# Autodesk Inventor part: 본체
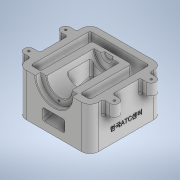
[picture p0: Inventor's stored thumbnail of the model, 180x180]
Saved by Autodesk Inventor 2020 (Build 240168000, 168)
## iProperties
Created: 2022-03
Part Number: 본체
Material: 일반
Document SubType Name: Modeling
Designer: Administrator
Density: 1 g/cm^3
Appearance: 기본값
Author: Administrator
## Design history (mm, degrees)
sketch "스케치1"
  geometry: L1 (-55, -55)-(55, -55); L2 (55, -55)-(55, 55); L3 (55, 55)-(-55, 55); L4 (-55, 55)-(-55, -55); L5 (-55, -55)-(55, 55); L6 (55, -55)-(-55, 55); 1 further point
  constraints: 12 end point, 2 midpoint, 2 parallel, 1 horizontal, 1 perpendicular
  dimensions: "d0" = 110 distance of L2.end L3.end; "d1" = 110 distance of L3.end L1.start
extrude "돌출1" new body sketch "스케치1" distance "d2" = 65; taper "d3" = 0 deg
sketch "스케치3"
  geometry: L1 (-45, 45)-(45, 45); L2 (-45, 45)-(-45, -45); L3 (-45, -45)-(-30, -45); L4 (-30, -45)-(-30, 33); L5 (-30, 33)-(30, 33); L6 (30, 33)-(30, -45); L7 (45, 45)-(45, -45); L8 (45, -45)-(30, -45); L9 (-55, 55)-(-55, -55) reference; L10 (55, -55)-(55, 55) reference; L11 (55, 55)-(-55, 55) reference; L12 (-55, -55)-(55, -55) reference; 1 further point
  constraints: 16 end point, 5 perpendicular, 2 vertical, 1 horizontal, 1 point on line
  dimensions: "d5" = 25 distance between parallel lines of L4 L9; "d7" = 25 distance between parallel lines of L6 L10; "d8" = 10 distance between parallel lines of L1 L11; "d9" = 12 distance between parallel lines of L1 L5; "d10" = 15 distance between parallel lines of L4 L2; "d11" = 15 distance between parallel lines of L6 L7; "d12" = 10 distance between parallel lines of L12 L3
extrude "돌출2" cut sketch "스케치3" extent not by distance; stored distance "d13" = 0; taper "d14" = 0 deg
sketch "스케치5"
  geometry: L1 (55, 65)-(-55, 65) reference; L2 (-55, 65)-(55, 65); L3 (-55, 0)-(-55, 65) reference; L4 (-55, 65)-(-55, 37); L5 (-55, 37)-(-47, 37); L6 (-45, 65)-(-45, 0) reference; L7 (-47, 37)-(-47, 46); L8 (-47, 46)-(25, 46); L9 (25, 46)-(25, 65); 2 further points
  constraints: 12 end point, 3 perpendicular, 2 point on line, 1 horizontal, 1 parallel
  dimensions: "d16" = 8 distance of L4.end L5.end; "d17" = 56 diameter of L5 L1; "d18" = 38 diameter of L8 L1; "d19" = 72 distance between parallel lines of L9 L7
revolve "회전1" sketch "스케치5" stored, may be unused: angle "d20" = 90 deg
node "작업 평면1"
sketch "스케치6"
  geometry: L1 (19, 0)-(-19, 0) reference; C1 r 6.5 at (0, 0); 3 further points
  constraints: 1 centre point, 1 midpoint
  dimensions: "d22" = 13 diameter of C1
extrude "돌출4" cut sketch "스케치6" stored distance "d25" = 10; taper "d26" = 30 deg
fillet "모깎기1" dims "d27" = 13
sketch "스케치7"
  geometry: L1 (-65, 35)-(-47.997, 35); L2 (-47.997, 35)-(-47.997, 21); L3 (-47.997, 21)-(-65, 21); L4 (-45, -45)-(-45, 45) reference; L5 (-55, 42)-(-55, -42) reference; L6 (42, 55)-(-42, 55) reference; A1 r 7 centre (-65, 28) between (-65, 35) and (-65, 21); 3 further points
  constraints: 6 end point, 2 point on circle, 1 centre point, 1 horizontal, 1 perpendicular, 1 tangent, 1 vertical alignment
  dimensions: "d29" = 10 distance from line of A1.centre L5; "d30" = 14 distance between parallel lines of L3 L1; "d31" = 27 distance from line of A1.centre L6
extrude "돌출5" join sketch "스케치7" distance "d32" = 20; taper "d33" = 0 deg
chamfer "모따기1" distance "d34" = 1; stored, may be unused: second distance "d35" = 2, angle "d36" = 45 deg
sketch "스케치8"
  geometry: A1 r 7 centre (-65, 28) between (-65, 35) and (-65, 21) reference; A2 r 7 centre (-65, -28) between (-65, -21) and (-65, -35) reference; A3 r 7 centre (65, -28) between (65, -35) and (65, -21) reference; A4 r 7 centre (65, 28) between (65, 21) and (65, 35) reference; 5 further points
  constraints: 4 coincident
hole "구멍1" sketch "스케치8" at (-65, 28), (-65, -28), (65, -28), (65, 28) diameter "d37" = 3.242; stored, may be unused: countersink angle "d41" = 90 deg, drill point angle "d43" = 118 deg; dims "d38" = 9, "d39" = 4, "d40" = 2, "d42" = 11
fillet "모깎기2" dims "d44" = 3
fillet "모깎기3" dims "d45" = 3
chamfer "모따기2" distance "d46" = 1; stored, may be unused: second distance "d47" = 2, angle "d48" = 45 deg
sketch "스케치10"
  geometry: L1 (-55, 0)-(-55, 65) reference; L2 (-55, 29.197)-(-19, 38.843); L3 (-55, 11.597)-(19, 31.425); L4 (33, 65)-(33, 0) reference; L5 (33, 30)-(-36.449, 11.391); L6 (-36.449, 11.391)-(-36.449, 0); L7 (-45, 0)-(33, 0) reference; L8 (-19, 57.482)-(19, 57.482); L9 (-19, 57.482)-(-19, 38.843); L10 (-18, 65)-(-18, 48) reference; L11 (19, 57.482)-(19, 31.425); L12 (18, 48)-(18, 65) reference; L13 (-55, 29.197)-(-55, 11.597); 1 further point
  constraints: 16 end point, 5 parallel, 4 point on line, 1 horizontal, 1 vertical
  dimensions: "d50" = 17 distance between parallel lines of L3 L2; "d51" = 30 distance from line of L5.start L7; "d52" = 75 deg angle of L4 L5; "d53" = 5 distance between parallel lines of L3 L5; "d54" = 36 distance from line of L8.start L1; "d55" = 38 distance of L8.end L8.start
extrude "돌출6" cut sketch "스케치10" stored distance "d56" = 34; taper "d57" = 0 deg
fillet "모깎기4" dims "d58" = 3
fillet "모깎기5" dims "d59" = 3
sketch "스케치11"
  geometry: L1 (0, 0)-(0, 84) reference; 3 further points
  constraints: 1 horizontal alignment, 1 midpoint, 1 other
  dimensions: "d60" = 20 distance of point (-20, 42) point (0, 42)
feature "엠보싱1" sketch "스케치11" dims "d0" = 110, "d1" = 110, "d12" = 10, "d61" = 0.5, "d62" = 0
sketch "스케치12" dims "d83" = 46
  geometry: L1 (-42, -65)-(42, -65) reference; L2 (-19, 0)-(-8.809, 0) reference; L3 (-6.5, 0)-(6.5, 0) reference; A1 r 6.5 centre (0, 0) between (-6.5, 0) and (6.5, 0) reference; 4 further points
  constraints: 2 vertical alignment, 1 midpoint, 3 other
hole "구멍2" sketch "스케치12" at (0, -23) diameter "d64" = 3.242; stored, may be unused: countersink angle "d68" = 90 deg, drill point angle "d70" = 118 deg; dims "d65" = 9, "d66" = 4, "d67" = 2, "d69" = 11
sketch "스케치14"
  geometry: L1 (33, 65)-(33, 0) reference; L2 (33, 30)-(-45, 9.1); L3 (-55, 11.597)-(16.776, 30.829) reference; L4 (-45, 9.1)-(-45, 0); L5 (-45, 0)-(33, 0) reference; L6 (-42, 0)-(-55, 0) reference; L7 (-55, 0)-(-55, 65) reference; 1 further point
  constraints: 4 end point, 1 parallel, 1 point on line, 1 vertical
  dimensions: "d71" = 5 distance between parallel lines of L3 L2; "d77" = 10 distance between parallel lines of L4 L7
extrude "돌출7" cut sketch "스케치14" stored distance "d72" = 60; taper "d73" = 0 deg
fillet "모깎기6" dims "d74" = 1
fillet "모깎기7" dims "d75" = 3
fillet "모깎기8" dims "d76" = 3
fillet "모깎기9" dims "d78" = 3
fillet "모깎기10" dims "d82" = 3
fillet "모깎기11" dims "d84" = 3
fillet "모깎기12" dims "d85" = 1
node "솔리드1"
mirror "미러1"
mirror "미러2"
feature "A9D066F2-1C7D-4E18-AEED-F7BC21143FA4" dims "d37" = 3.242, "d38" = 9, "d39" = 4, "d40" = 2, "d41" = 90 deg, "d42" = 11, "d43" = 118 deg
other parameters: "d21" = -4
